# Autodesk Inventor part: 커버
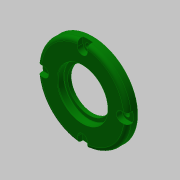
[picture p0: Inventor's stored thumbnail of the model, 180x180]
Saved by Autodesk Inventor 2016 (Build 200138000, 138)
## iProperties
Created: 2019-05
Part Number: 커버
Material: 알루미늄 6061
Document SubType Name: Modeling
Designer: mduedu
Density: 1 g/cm^3
Appearance: 진녹색
Author: mduedu
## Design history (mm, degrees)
sketch "스케치1"
  geometry: L1 (0, 0)-(36, 0); L2 (36, 0)-(36, -8); L3 (36, -8)-(0, -8); L4 (0, -8)-(0, 0); L5 (0, -8)-(26, -8); L6 (26, -8)-(26, -12); L7 (26, -12)-(0, -12); L8 (0, -12)-(0, -8)
  constraints: 16 end point, 4 parallel, 2 horizontal, 2 perpendicular
  dimensions: "d0" = 72 diameter of L2 L4; "d2" = 52 diameter of L6 L8; "d3" = 12 distance between parallel lines of L7 L1; "d4" = 4 distance between parallel lines of L7 L3
revolve "회전1" sketch "스케치1" stored, may be unused: angle "d5" = 90 deg
sketch "스케치2" dims "d6" = 62
  geometry: L1 (-4, 31)-(-4, 35.777); L2 (4, 31)-(4, 35.777); A1 r 4 centre (0, 31) between (-4, 31) and (4, 31); A2 r 36 centre (0, 0) between (-4, 35.777) and (4, 35.777) reference; A3 r 36 centre (0, 0) between (4, 35.777) and (-4, 35.777); 2 further points
  constraints: 6 point on circle, 4 end point, 2 centre point, 2 coincident, 2 tangent, 2 vertical alignment, 1 parallel, 1 vertical, 2 other
  dimensions: "d7" = 8 distance between parallel lines of L2 L1
extrude "돌출1" cut sketch "스케치2" distance "d8" = 4.4; taper "d9" = 0 deg
fillet "모깎기1" dims "d13" = 3
sketch "스케치3"
  geometry: L1 (36, -4.4)-(36, -8) reference; L2 (36, -8)-(26, -8) reference; L3 (26, -8)-(26, -12) reference; L4 (26, -12)-(-26, -12) reference; L5 (-26, -12)-(-26, -8) reference; L6 (-26, -8)-(-36, -8) reference; L7 (-36, -8)-(-36, -4.4) reference; L8 (-36, -4.4)-(-27, -4.4) reference; L9 (-27, -4.4)-(-27, 0) reference; L10 (-27, 0)-(27, 0) reference; L11 (27, 0)-(27, -4.4) reference; L12 (27, -4.4)-(36, -4.4) reference; L13 (0, 0)-(20, 0); L14 (20, 0)-(20, -5.2); L15 (20, -5.2)-(0, -5.2); L16 (0, -5.2)-(0, 0); L17 (0, -5.2)-(17, -5.2); L18 (17, -5.2)-(17, -8); L19 (17, -8)-(0, -8); L20 (0, -8)-(0, -5.2); L21 (0, -8)-(23, -8); L22 (23, -8)-(23, -12); L23 (23, -12)-(0, -12); L24 (0, -12)-(0, -8)
  constraints: 24 end point, 6 parallel, 3 horizontal, 3 perpendicular, 1 point on line
  dimensions: "d14" = 40 diameter of L14 L16; "d16" = 5.2 distance of L13.end L14.end; "d17" = 46 diameter of L22 L24; "d18" = 4 distance of L21.end L22.end; "d19" = 34 diameter of L18 L20
revolve "회전2" sketch "스케치3" stored, may be unused: angle "d20" = 90 deg
chamfer "모따기1" distance "d21" = 0.5; stored, may be unused: second distance "d22" = 2, angle "d23" = 30 deg
fillet "모깎기2" dims "d24" = 0.2
fillet "모깎기3" dims "d25" = 3
chamfer "모따기2" distance "d26" = 1; stored, may be unused: second distance "d27" = 2, angle "d28" = 30 deg
sketch "스케치4" dims "d29" = 62
  geometry: 6 further points
  constraints: 2 vertical alignment, 1 coincident, 7 other
  dimensions: "d32" = 360 deg dimension on point (0, 0) point (0, 31) (derived)
sketch "스케치5"
  geometry: 4 further points
  constraints: 4 other
hole "구멍1" sketch "스케치5" at (-31, 0), (0, -31), (31, 0), (0, 31) diameter "d34" = 4.5; stored, may be unused: countersink angle "d38" = 90 deg, drill point angle "d40" = 0 deg; dims "d35" = 6, "d36" = 4, "d37" = 2, "d39" = 8
node "솔리드1"
pattern_circular "원형 패턴1" dims angle "d11" = 360 deg
node "절단 모서리 투영1"
